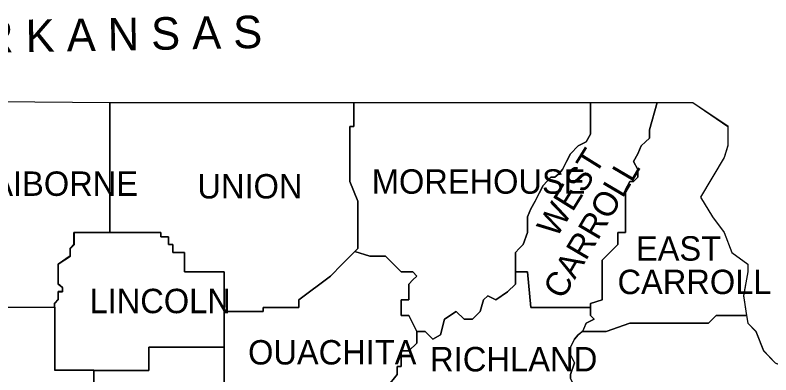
# Model space of a CAD drawing. Extents: x 0.19 to 2.82, y 0.04 to 1.79.
# Drawn here: x 2.2917 to 2.4368, y 1.6976 to 1.7666 of the extents above; entities that cross this region are included whole.
import ezdxf

# ---------------------------------------------------------------- set-up
doc = ezdxf.new("R2010")
doc.units = 0
for name, color, linetype in [('Dist04', 7, 'Continuous'), ('Dist05', 7, 'Continuous'), ('Standard Info', 7, 'Continuous')]:
    doc.layers.add(name, color=color, linetype=linetype)

msp = doc.modelspace()

# ---------------------------------------------------------------- linework, layer by layer
at = {"layer": 'Dist04'}
msp.add_line((2.27282, 1.75017), (2.3099, 1.74983), dxfattribs=at)
for points in [[(2.3099, 1.74983), (2.3099, 1.72492)], [(2.3099, 1.72492), (2.30299, 1.72492), (2.30299, 1.72267), (2.30224, 1.72192), (2.30224, 1.72042), (2.29999, 1.71883), (2.29999, 1.71508), (2.30082, 1.71433), (2.30082, 1.71358), (2.29999, 1.71358), (2.29999, 1.71208), (2.29924, 1.71133), (2.29924, 1.7105)], [(2.29932, 1.71058), (2.29932, 1.6985), (2.30682, 1.6985)], [(2.30682, 1.6985), (2.30682, 1.67958), (2.3054, 1.67883), (2.3054, 1.6765), (2.3054, 1.67575), (2.3039, 1.67575), (2.30307, 1.67508), (2.30307, 1.67275)]]:
    msp.add_lwpolyline(points, dxfattribs=at)
at = {"layer": 'Dist05'}
for p, q in [((2.3099, 1.74983), (2.35674, 1.74983)), ((2.35674, 1.74983), (2.40215, 1.74983)), ((2.40215, 1.74983), (2.41499, 1.74983)), ((2.41499, 1.74983), (2.42182, 1.74983))]:
    msp.add_line(p, q, dxfattribs=at)
for points in [[(2.3099, 1.72492), (2.3099, 1.74983)], [(2.42182, 1.74983), (2.42857, 1.74533), (2.42857, 1.74158), (2.42782, 1.73925), (2.42332, 1.73167), (2.42557, 1.72792), (2.42782, 1.72492), (2.42932, 1.72108), (2.4324, 1.71883), (2.4324, 1.71733), (2.43157, 1.71283), (2.43215, 1.709)], [(2.29924, 1.7105), (2.29924, 1.71133), (2.29999, 1.71208), (2.29999, 1.71358), (2.30082, 1.71358), (2.30082, 1.71433), (2.29999, 1.71508), (2.29999, 1.71883), (2.30224, 1.72042), (2.30224, 1.72192), (2.30299, 1.72267), (2.30299, 1.72492), (2.3099, 1.72492)], [(2.30682, 1.6985), (2.29932, 1.6985), (2.29932, 1.71058)], [(2.43215, 1.709), (2.4324, 1.7075), (2.4339, 1.706), (2.4354, 1.70225), (2.43765, 1.69992), (2.43915, 1.69925), (2.44065, 1.69542), (2.43999, 1.69083), (2.43765, 1.68483), (2.43615, 1.68333), (2.43615, 1.68258), (2.43474, 1.67875)], [(2.30307, 1.67275), (2.30307, 1.67508), (2.3039, 1.67575), (2.3054, 1.67575), (2.3054, 1.6765), (2.3054, 1.67883), (2.30682, 1.67958), (2.30682, 1.6985)]]:
    msp.add_lwpolyline(points, dxfattribs=at)
at = {"layer": 'Standard Info'}
for p, q in [((2.27282, 1.75017), (2.3099, 1.74983)), ((2.3099, 1.74983), (2.35674, 1.74983)), ((2.35674, 1.74983), (2.40215, 1.74983)), ((2.40215, 1.74983), (2.41499, 1.74983)), ((2.41499, 1.74983), (2.42182, 1.74983)), ((2.3569, 1.72125), (2.35749, 1.72183)), ((2.40057, 1.70592), (2.40049, 1.70592))]:
    msp.add_line(p, q, dxfattribs=at)
for points in [[(2.3099, 1.74983), (2.3099, 1.72492)], [(2.3099, 1.72492), (2.3099, 1.74983)], [(2.35674, 1.74983), (2.35674, 1.74525), (2.35599, 1.74525), (2.35599, 1.743), (2.35599, 1.73467), (2.35749, 1.73092), (2.35749, 1.72792), (2.35749, 1.72492), (2.35749, 1.72183), (2.35674, 1.72108), (2.35449, 1.71883), (2.35224, 1.7165), (2.34615, 1.712), (2.34615, 1.7105), (2.33932, 1.7105), (2.33932, 1.70975), (2.33182, 1.70975)], [(2.35749, 1.72183), (2.35749, 1.72492), (2.35749, 1.72792), (2.35749, 1.73092), (2.35599, 1.73467), (2.35599, 1.743), (2.35599, 1.74525), (2.35674, 1.74525), (2.35674, 1.74983)], [(2.38774, 1.71733), (2.38774, 1.71883), (2.38774, 1.72108), (2.38849, 1.72183), (2.38924, 1.72258), (2.39007, 1.72492), (2.39007, 1.72792), (2.39074, 1.72942), (2.39157, 1.73092), (2.39232, 1.73242), (2.39307, 1.73392), (2.39457, 1.7355), (2.39532, 1.7355), (2.39607, 1.73617), (2.39682, 1.737), (2.39757, 1.7385), (2.39832, 1.74), (2.39982, 1.7415), (2.40132, 1.74225), (2.40215, 1.74375), (2.40215, 1.74458), (2.40215, 1.74983)], [(2.40215, 1.74983), (2.40215, 1.74458), (2.40215, 1.74375), (2.40132, 1.74225), (2.39982, 1.7415), (2.39832, 1.74), (2.39757, 1.7385), (2.39682, 1.737), (2.39607, 1.73617), (2.39532, 1.7355), (2.39457, 1.7355), (2.39307, 1.73392), (2.39232, 1.73242), (2.39157, 1.73092), (2.39074, 1.72942), (2.39007, 1.72792), (2.39007, 1.72492), (2.38924, 1.72258), (2.38849, 1.72183), (2.38774, 1.72108), (2.38774, 1.71883), (2.38774, 1.71733)], [(2.38774, 1.71733), (2.38774, 1.71883), (2.38774, 1.72108), (2.38849, 1.72183), (2.38924, 1.72258), (2.39007, 1.72492), (2.39007, 1.72792), (2.39074, 1.72942), (2.39157, 1.73092), (2.39232, 1.73242), (2.39307, 1.73392), (2.39457, 1.7355), (2.39532, 1.7355), (2.39607, 1.73617), (2.39682, 1.737), (2.39757, 1.7385), (2.39832, 1.74), (2.39982, 1.7415), (2.40132, 1.74225), (2.40215, 1.74375), (2.40215, 1.74458), (2.40215, 1.74983)], [(2.40074, 1.70608), (2.40132, 1.7075), (2.4029, 1.70825), (2.40215, 1.709), (2.40215, 1.7105), (2.40215, 1.71125), (2.4044, 1.712), (2.4044, 1.71275), (2.4044, 1.7135), (2.4044, 1.71433), (2.4044, 1.71583), (2.4044, 1.71733), (2.4044, 1.71958), (2.40515, 1.72033), (2.4059, 1.72108), (2.40665, 1.72183), (2.4074, 1.72258), (2.4074, 1.72492), (2.4089, 1.72492), (2.4089, 1.73317), (2.40974, 1.73467), (2.4104, 1.73467), (2.41124, 1.7355), (2.41124, 1.737), (2.4104, 1.7385), (2.41124, 1.74), (2.4119, 1.7415), (2.41274, 1.74225), (2.41349, 1.743), (2.41349, 1.74458), (2.41499, 1.74983)], [(2.41499, 1.74983), (2.41349, 1.74458), (2.41349, 1.743), (2.41274, 1.74225), (2.4119, 1.7415), (2.41124, 1.74), (2.4104, 1.7385), (2.41124, 1.737), (2.41124, 1.7355), (2.4104, 1.73467), (2.40974, 1.73467), (2.4089, 1.73317), (2.4089, 1.72492), (2.4074, 1.72492), (2.4074, 1.72258), (2.40665, 1.72183), (2.4059, 1.72108), (2.40515, 1.72033), (2.4044, 1.71958), (2.4044, 1.71733), (2.4044, 1.71583), (2.4044, 1.71433), (2.4044, 1.7135), (2.4044, 1.71275), (2.4044, 1.712), (2.40215, 1.71125), (2.40215, 1.7105)], [(2.42182, 1.74983), (2.42857, 1.74525), (2.42857, 1.7415), (2.42782, 1.73925), (2.42332, 1.73167), (2.42557, 1.72792), (2.42782, 1.72492), (2.42932, 1.72108), (2.4324, 1.71883), (2.4324, 1.71733), (2.43157, 1.71275), (2.43215, 1.709)], [(2.3099, 1.72492), (2.30299, 1.72492), (2.30299, 1.72258), (2.30224, 1.72183), (2.30224, 1.72033), (2.29999, 1.71883), (2.29999, 1.715), (2.30082, 1.71433), (2.30082, 1.7135), (2.29999, 1.7135), (2.29999, 1.712), (2.29924, 1.71125), (2.29924, 1.7105)], [(2.29932, 1.7105), (2.29932, 1.71125), (2.29999, 1.712), (2.29999, 1.7135), (2.30082, 1.7135), (2.30082, 1.71433), (2.29999, 1.715), (2.29999, 1.71883), (2.30232, 1.72033), (2.30232, 1.72183), (2.30307, 1.72258), (2.30307, 1.72492), (2.3099, 1.72492)], [(2.29932, 1.7105), (2.29932, 1.71125), (2.29999, 1.712), (2.29999, 1.7135), (2.30082, 1.7135), (2.30082, 1.71433), (2.29999, 1.715), (2.29999, 1.71883), (2.30232, 1.72033), (2.30232, 1.72183), (2.30307, 1.72258), (2.30307, 1.72492), (2.3099, 1.72492)], [(2.33182, 1.70975), (2.33182, 1.71733), (2.32424, 1.71733), (2.32424, 1.72108), (2.32199, 1.72108), (2.32199, 1.72258), (2.32115, 1.72258), (2.32115, 1.72408), (2.31965, 1.72408), (2.31965, 1.72492), (2.3099, 1.72492)], [(2.3099, 1.72492), (2.31965, 1.72492), (2.31965, 1.72408), (2.32115, 1.72408), (2.32115, 1.72258), (2.32199, 1.72258), (2.32199, 1.72108), (2.32424, 1.72108), (2.32424, 1.71733), (2.33182, 1.71733), (2.33182, 1.70975), (2.33182, 1.70292)], [(2.33182, 1.70975), (2.33932, 1.70975), (2.33932, 1.7105), (2.34615, 1.7105), (2.34615, 1.712), (2.35224, 1.7165), (2.35449, 1.71883), (2.3569, 1.72125)], [(2.3569, 1.72125), (2.35982, 1.72033), (2.36282, 1.72033), (2.36432, 1.71883), (2.36582, 1.71733), (2.36807, 1.71733), (2.36882, 1.7165), (2.36807, 1.71583), (2.36732, 1.715), (2.36732, 1.712), (2.36582, 1.712), (2.36582, 1.709), (2.36732, 1.709), (2.36882, 1.70592), (2.36882, 1.70367), (2.36732, 1.70217), (2.36582, 1.70217), (2.36582, 1.69917), (2.36507, 1.69917), (2.36507, 1.69767), (2.36132, 1.69308), (2.36132, 1.68783), (2.36049, 1.68783), (2.36049, 1.68408)], [(2.36882, 1.70592), (2.36732, 1.709), (2.36582, 1.709), (2.36582, 1.712), (2.36732, 1.712), (2.36732, 1.715), (2.36807, 1.71583), (2.36882, 1.7165), (2.36807, 1.71733), (2.36582, 1.71733), (2.36432, 1.71883), (2.36282, 1.72033), (2.35982, 1.72033), (2.3569, 1.72125)], [(2.38774, 1.71733), (2.38774, 1.715), (2.38624, 1.7135), (2.38399, 1.712), (2.38249, 1.71275), (2.38165, 1.712), (2.38099, 1.70975), (2.37949, 1.70825), (2.3779, 1.70825), (2.3764, 1.70975), (2.37415, 1.70825), (2.3734, 1.70525), (2.3719, 1.70442), (2.3704, 1.70592), (2.36882, 1.70592)], [(2.36882, 1.70592), (2.3704, 1.70592), (2.3719, 1.70442), (2.3734, 1.70525), (2.37415, 1.70825), (2.3764, 1.70975), (2.3779, 1.70825), (2.37949, 1.70825), (2.38099, 1.70975), (2.38165, 1.712), (2.38249, 1.71275), (2.38399, 1.712), (2.38624, 1.7135), (2.38774, 1.715), (2.38774, 1.71733)], [(2.40215, 1.7105), (2.39074, 1.7105), (2.39007, 1.71733), (2.38774, 1.71733)], [(2.38774, 1.71733), (2.39007, 1.71733), (2.39074, 1.7105), (2.40215, 1.7105)], [(2.29924, 1.7105), (2.27765, 1.7105)], [(2.27774, 1.71058), (2.29932, 1.71058)], [(2.29932, 1.71058), (2.29932, 1.6985), (2.30682, 1.6985)], [(2.30682, 1.69842), (2.29932, 1.69842), (2.29932, 1.7105)], [(2.34015, 1.68408), (2.34015, 1.68783), (2.33182, 1.69533), (2.33182, 1.70292), (2.33182, 1.70975)], [(2.40215, 1.7105), (2.40215, 1.709), (2.4029, 1.70825), (2.40132, 1.7075), (2.40065, 1.70592), (2.39982, 1.70525), (2.39907, 1.70442), (2.39832, 1.70292), (2.39832, 1.70217), (2.39832, 1.70142), (2.39907, 1.69992), (2.39832, 1.69767), (2.39832, 1.69692), (2.39907, 1.69533)], [(2.43215, 1.709), (2.42632, 1.709), (2.42482, 1.7075), (2.40974, 1.7075), (2.40515, 1.70592), (2.40049, 1.70592)], [(2.40049, 1.70592), (2.40515, 1.70592), (2.40974, 1.7075), (2.42482, 1.7075), (2.42632, 1.709), (2.43215, 1.709)], [(2.43215, 1.709), (2.4324, 1.7075), (2.4339, 1.70592), (2.4354, 1.70217), (2.43765, 1.69992), (2.43915, 1.69917), (2.44065, 1.69533), (2.43999, 1.69083), (2.43765, 1.68475), (2.43615, 1.68325), (2.43615, 1.6825), (2.43474, 1.67867)], [(2.36049, 1.68408), (2.36049, 1.68783), (2.36132, 1.68783), (2.36132, 1.69308), (2.36507, 1.69767), (2.36507, 1.69917), (2.36582, 1.69917), (2.36582, 1.70217), (2.36732, 1.70217), (2.36882, 1.70367), (2.36882, 1.70592)], [(2.39907, 1.69533), (2.39832, 1.69692), (2.39832, 1.69767), (2.39907, 1.69992), (2.39832, 1.70142), (2.39832, 1.70217), (2.39832, 1.70292), (2.39907, 1.70442), (2.39982, 1.70525), (2.40057, 1.70592)], [(2.33182, 1.70292), (2.3174, 1.70292), (2.3174, 1.69842), (2.30682, 1.69842)], [(2.30682, 1.69842), (2.3174, 1.69842), (2.3174, 1.70292), (2.33182, 1.70292)], [(2.33182, 1.70292), (2.33182, 1.69533), (2.34015, 1.68783), (2.34015, 1.68408)], [(2.30682, 1.6985), (2.30682, 1.67958), (2.3054, 1.67875), (2.3054, 1.6765), (2.3054, 1.67575), (2.3039, 1.67575), (2.30307, 1.675), (2.30307, 1.67267)], [(2.30307, 1.67267), (2.30307, 1.675), (2.30382, 1.67567), (2.30532, 1.67567), (2.30532, 1.6765), (2.30532, 1.67875), (2.30682, 1.6795), (2.30682, 1.69842)]]:
    msp.add_lwpolyline(points, dxfattribs=at)

# ---------------------------------------------------------------- texts
for s, height, rotation, p in [('A R K A N S A S', 0.0062368, 1.0059, (2.27755, 1.7592)), ('WEST', 0.004679, 58.1411, (2.3956, 1.72366)), ('CARROLL', 0.004679, 59.4887, (2.39686, 1.71184))]:
    msp.add_text(s, height=height, rotation=rotation, dxfattribs=at).set_placement(p)
for s, height, p in [('MOREHOUSE', 0.004679, (2.36018, 1.73233)), ('CLAIBORNE', 0.004679, (2.27913, 1.73192)), ('UNION', 0.004679, (2.3267, 1.73142)), ('EAST', 0.004679, (2.4109, 1.7195)), ('CARROLL', 0.004679, (2.40736, 1.71308)), ('LINCOLN', 0.004679, (2.30599, 1.70942)), ('OUACHITA', 0.004679, (2.33642, 1.69958)), ('RICHLAND', 0.0047, (2.37136, 1.69825))]:
    msp.add_text(s, height=height, dxfattribs=at).set_placement(p)

doc.saveas('drawing.dxf')
